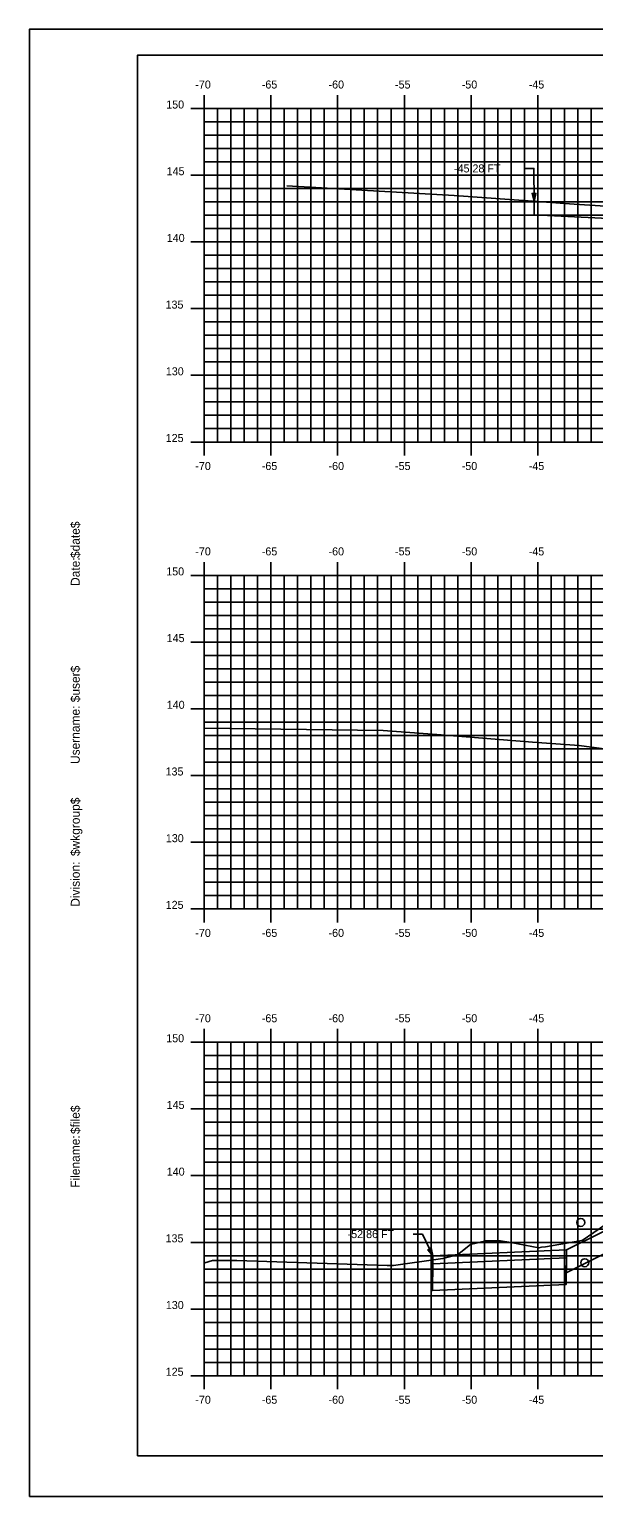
# Model space of a CAD drawing. Extents: x 1144085 to 1144255, y 608981 to 609091.
# Drawn here: x 1144085.3 to 1144127.5, y 608981.3 to 609091.3 of the extents above; entities that cross this region are included whole.
import ezdxf

# ---------------------------------------------------------------- set-up
doc = ezdxf.new("R2010")
doc.units = 0
for name, color, linetype in [('BORDER', 7, 'Continuous'), ('D_Roadway_SubGrade', 7, 'Continuous'), ('D_Text_Standard', 7, 'Continuous'), ('H_V ANNOTATION', 7, 'Continuous'), ('MAJOR', 7, 'Continuous'), ('MINOR', 7, 'Continuous'), ('PATTERNING', 7, 'Continuous'), ('PLOT BOUNDARY', 7, 'Continuous'), ('S_Drainage_Invert', 7, 'Continuous'), ('S_Roadway_Centerline', 7, 'Continuous')]:
    doc.layers.add(name, color=color, linetype=linetype)

msp = doc.modelspace()

# ---------------------------------------------------------------- linework, layer by layer
msp.add_lwpolyline([(1144123.07, 609078.38), (1144153.35, 609078.29), (1144157.35, 609078.45), (1144168.35, 609078.67), (1144179.35, 609078.45), (1144188.75, 609078.08), (1144196.13, 609075.62), (1144199.13, 609074.62), (1144217.63, 609068.45)])
at = {"layer": 'BORDER'}
msp.add_lwpolyline([(1144093.35, 608984.34), (1144253.35, 608984.34), (1144253.35, 609089.34), (1144093.35, 609089.34)], close=True, dxfattribs=at)
at = {"layer": 'D_Roadway_SubGrade'}
msp.add_lwpolyline([(1144123.07, 609077.38), (1144153.35, 609075.87), (1144157.35, 609075.95), (1144157.35, 609078.04), (1144157.35, 609078.2), (1144153.35, 609078.04), (1144153.35, 609078.29), (1144123.07, 609078.38)], close=True, dxfattribs=at)
at = {"layer": 'D_Text_Standard'}
for points in [[(1144123.07, 609078.38), (1144123.05, 609080.85), (1144122.37, 609080.85)], [(1144115.49, 608999.33), (1144114.7, 609000.96), (1144114.02, 609000.96)]]:
    msp.add_lwpolyline(points, dxfattribs=at)
for points in [[(1144123.07, 609078.38), (1144122.92, 609078.97), (1144123.21, 609078.97)], [(1144115.49, 608999.33), (1144115.11, 608999.79), (1144115.37, 608999.92)]]:
    msp.add_lwpolyline(points, close=True, dxfattribs=at)
at = {"layer": 'MAJOR'}
for p, q in [((1144098.35, 609086.34), (1144098.35, 609085.34)), ((1144103.35, 609086.34), (1144103.35, 609085.34)), ((1144108.35, 609086.34), (1144108.35, 609085.34)), ((1144113.35, 609086.34), (1144113.35, 609085.34)), ((1144118.35, 609086.34), (1144118.35, 609085.34)), ((1144123.35, 609086.34), (1144123.35, 609085.34)), ((1144097.35, 609085.34), (1144098.35, 609085.34)), ((1144098.35, 609085.34), (1144238.35, 609085.34)), ((1144098.35, 609060.34), (1144098.35, 609085.34)), ((1144098.35, 609060.34), (1144098.35, 609085.34)), ((1144098.35, 609085.34), (1144238.35, 609085.34)), ((1144103.35, 609060.34), (1144103.35, 609085.34)), ((1144108.35, 609060.34), (1144108.35, 609085.34)), ((1144113.35, 609060.34), (1144113.35, 609085.34)), ((1144118.35, 609060.34), (1144118.35, 609085.34)), ((1144123.35, 609060.34), (1144123.35, 609085.34)), ((1144097.35, 609080.34), (1144098.35, 609080.34)), ((1144098.35, 609080.34), (1144238.35, 609080.34)), ((1144097.35, 609075.34), (1144098.35, 609075.34)), ((1144098.35, 609075.34), (1144238.35, 609075.34)), ((1144097.35, 609070.34), (1144098.35, 609070.34)), ((1144098.35, 609070.34), (1144238.35, 609070.34)), ((1144097.35, 609065.34), (1144098.35, 609065.34)), ((1144098.35, 609065.34), (1144238.35, 609065.34)), ((1144097.35, 609060.34), (1144098.35, 609060.34)), ((1144098.35, 609060.34), (1144238.35, 609060.34)), ((1144098.35, 609060.34), (1144238.35, 609060.34)), ((1144098.35, 609059.33), (1144098.35, 609060.34)), ((1144103.35, 609059.33), (1144103.35, 609060.34)), ((1144108.35, 609059.33), (1144108.35, 609060.34)), ((1144113.35, 609059.33), (1144113.35, 609060.34)), ((1144118.35, 609059.33), (1144118.35, 609060.34)), ((1144123.35, 609059.33), (1144123.35, 609060.34)), ((1144098.35, 609051.34), (1144098.35, 609050.34)), ((1144103.35, 609051.34), (1144103.35, 609050.34)), ((1144108.35, 609051.34), (1144108.35, 609050.34)), ((1144113.35, 609051.34), (1144113.35, 609050.34)), ((1144118.35, 609051.34), (1144118.35, 609050.34)), ((1144123.35, 609051.34), (1144123.35, 609050.34)), ((1144097.35, 609050.34), (1144098.35, 609050.34)), ((1144098.35, 609050.34), (1144238.35, 609050.34)), ((1144098.35, 609025.34), (1144098.35, 609050.34)), ((1144098.35, 609025.34), (1144098.35, 609050.34)), ((1144098.35, 609050.34), (1144238.35, 609050.34)), ((1144103.35, 609025.34), (1144103.35, 609050.34)), ((1144108.35, 609025.34), (1144108.35, 609050.34)), ((1144113.35, 609025.34), (1144113.35, 609050.34)), ((1144118.35, 609025.34), (1144118.35, 609050.34)), ((1144123.35, 609025.34), (1144123.35, 609050.34)), ((1144097.35, 609045.34), (1144098.35, 609045.34)), ((1144098.35, 609045.34), (1144238.35, 609045.34)), ((1144097.35, 609040.34), (1144098.35, 609040.34)), ((1144098.35, 609040.34), (1144238.35, 609040.34)), ((1144097.35, 609035.34), (1144098.35, 609035.34)), ((1144098.35, 609035.34), (1144238.35, 609035.34)), ((1144097.35, 609030.34), (1144098.35, 609030.34)), ((1144098.35, 609030.34), (1144238.35, 609030.34)), ((1144097.35, 609025.34), (1144098.35, 609025.34)), ((1144098.35, 609025.34), (1144238.35, 609025.34)), ((1144098.35, 609025.34), (1144238.35, 609025.34)), ((1144098.35, 609024.33), (1144098.35, 609025.34)), ((1144103.35, 609024.33), (1144103.35, 609025.34)), ((1144108.35, 609024.33), (1144108.35, 609025.34)), ((1144113.35, 609024.33), (1144113.35, 609025.34)), ((1144118.35, 609024.33), (1144118.35, 609025.34)), ((1144123.35, 609024.33), (1144123.35, 609025.34)), ((1144098.35, 609016.34), (1144098.35, 609015.34)), ((1144103.35, 609016.34), (1144103.35, 609015.34)), ((1144108.35, 609016.34), (1144108.35, 609015.34)), ((1144113.35, 609016.34), (1144113.35, 609015.34)), ((1144118.35, 609016.34), (1144118.35, 609015.34)), ((1144123.35, 609016.34), (1144123.35, 609015.34)), ((1144097.35, 609015.34), (1144098.35, 609015.34)), ((1144098.35, 609015.34), (1144238.35, 609015.34)), ((1144098.35, 608990.34), (1144098.35, 609015.34)), ((1144098.35, 608990.34), (1144098.35, 609015.34)), ((1144098.35, 609015.34), (1144238.35, 609015.34)), ((1144103.35, 608990.34), (1144103.35, 609015.34)), ((1144108.35, 608990.34), (1144108.35, 609015.34)), ((1144113.35, 608990.34), (1144113.35, 609015.34)), ((1144118.35, 608990.34), (1144118.35, 609015.34)), ((1144123.35, 608990.34), (1144123.35, 609015.34)), ((1144097.35, 609010.34), (1144098.35, 609010.34)), ((1144098.35, 609010.34), (1144238.35, 609010.34)), ((1144097.35, 609005.34), (1144098.35, 609005.34)), ((1144098.35, 609005.34), (1144238.35, 609005.34)), ((1144097.35, 609000.34), (1144098.35, 609000.34)), ((1144098.35, 609000.34), (1144238.35, 609000.34)), ((1144097.35, 608995.34), (1144098.35, 608995.34)), ((1144098.35, 608995.34), (1144238.35, 608995.34)), ((1144097.35, 608990.34), (1144098.35, 608990.34)), ((1144098.35, 608990.34), (1144238.35, 608990.34)), ((1144098.35, 608990.34), (1144238.35, 608990.34)), ((1144098.35, 608989.33), (1144098.35, 608990.34)), ((1144103.35, 608989.33), (1144103.35, 608990.34)), ((1144108.35, 608989.33), (1144108.35, 608990.34)), ((1144113.35, 608989.33), (1144113.35, 608990.34)), ((1144118.35, 608989.33), (1144118.35, 608990.34)), ((1144123.35, 608989.33), (1144123.35, 608990.34))]:
    msp.add_line(p, q, dxfattribs=at)
at = {"layer": 'MINOR'}
for p, q in [((1144098.35, 609084.34), (1144238.35, 609084.34)), ((1144098.35, 609084.34), (1144099.35, 609084.34)), ((1144099.35, 609060.34), (1144099.35, 609085.34)), ((1144100.35, 609060.34), (1144100.35, 609085.34)), ((1144101.35, 609060.34), (1144101.35, 609085.34)), ((1144102.35, 609060.34), (1144102.35, 609085.34)), ((1144104.35, 609060.34), (1144104.35, 609085.34)), ((1144105.35, 609060.34), (1144105.35, 609085.34)), ((1144106.35, 609060.34), (1144106.35, 609085.34)), ((1144107.35, 609060.34), (1144107.35, 609085.34)), ((1144109.35, 609060.34), (1144109.35, 609085.34)), ((1144110.35, 609060.34), (1144110.35, 609085.34)), ((1144111.35, 609060.34), (1144111.35, 609085.34)), ((1144112.35, 609060.34), (1144112.35, 609085.34)), ((1144114.35, 609060.34), (1144114.35, 609085.34)), ((1144115.35, 609060.34), (1144115.35, 609085.34)), ((1144116.35, 609060.34), (1144116.35, 609085.34)), ((1144117.35, 609060.34), (1144117.35, 609085.34)), ((1144119.35, 609060.34), (1144119.35, 609085.34)), ((1144120.35, 609060.34), (1144120.35, 609085.34)), ((1144121.35, 609060.34), (1144121.35, 609085.34)), ((1144122.35, 609060.34), (1144122.35, 609085.34)), ((1144124.35, 609060.34), (1144124.35, 609085.34)), ((1144125.35, 609060.34), (1144125.35, 609085.34)), ((1144126.35, 609060.34), (1144126.35, 609085.34)), ((1144127.35, 609060.34), (1144127.35, 609085.34)), ((1144098.35, 609083.34), (1144238.35, 609083.34)), ((1144098.35, 609083.34), (1144099.35, 609083.34)), ((1144098.35, 609082.34), (1144238.35, 609082.34)), ((1144098.35, 609082.34), (1144099.35, 609082.34)), ((1144098.35, 609081.34), (1144238.35, 609081.34)), ((1144098.35, 609081.34), (1144099.35, 609081.34)), ((1144098.35, 609079.34), (1144238.35, 609079.34)), ((1144098.35, 609079.34), (1144099.35, 609079.34)), ((1144098.35, 609078.34), (1144238.35, 609078.34)), ((1144098.35, 609078.34), (1144099.35, 609078.34)), ((1144098.35, 609077.34), (1144238.35, 609077.34)), ((1144098.35, 609077.34), (1144099.35, 609077.34)), ((1144098.35, 609076.34), (1144238.35, 609076.34)), ((1144098.35, 609076.34), (1144099.35, 609076.34)), ((1144098.35, 609074.34), (1144238.35, 609074.34)), ((1144098.35, 609074.34), (1144099.35, 609074.34)), ((1144098.35, 609073.34), (1144238.35, 609073.34)), ((1144098.35, 609073.34), (1144099.35, 609073.34)), ((1144098.35, 609072.34), (1144238.35, 609072.34)), ((1144098.35, 609072.34), (1144099.35, 609072.34)), ((1144098.35, 609071.34), (1144238.35, 609071.34)), ((1144098.35, 609071.34), (1144099.35, 609071.34)), ((1144098.35, 609069.34), (1144238.35, 609069.34)), ((1144098.35, 609069.34), (1144099.35, 609069.34)), ((1144098.35, 609068.34), (1144238.35, 609068.34)), ((1144098.35, 609068.34), (1144099.35, 609068.34)), ((1144098.35, 609067.34), (1144238.35, 609067.34)), ((1144098.35, 609067.34), (1144099.35, 609067.34)), ((1144098.35, 609066.34), (1144238.35, 609066.34)), ((1144098.35, 609066.34), (1144099.35, 609066.34)), ((1144098.35, 609064.34), (1144238.35, 609064.34)), ((1144098.35, 609064.34), (1144099.35, 609064.34)), ((1144098.35, 609063.34), (1144238.35, 609063.34)), ((1144098.35, 609063.34), (1144099.35, 609063.34)), ((1144098.35, 609062.34), (1144238.35, 609062.34)), ((1144098.35, 609062.34), (1144099.35, 609062.34)), ((1144098.35, 609061.34), (1144238.35, 609061.34)), ((1144098.35, 609061.34), (1144099.35, 609061.34)), ((1144099.35, 609025.34), (1144099.35, 609050.34)), ((1144100.35, 609025.34), (1144100.35, 609050.34)), ((1144101.35, 609025.34), (1144101.35, 609050.34)), ((1144102.35, 609025.34), (1144102.35, 609050.34)), ((1144104.35, 609025.34), (1144104.35, 609050.34)), ((1144105.35, 609025.34), (1144105.35, 609050.34)), ((1144106.35, 609025.34), (1144106.35, 609050.34)), ((1144107.35, 609025.34), (1144107.35, 609050.34)), ((1144109.35, 609025.34), (1144109.35, 609050.34)), ((1144110.35, 609025.34), (1144110.35, 609050.34)), ((1144111.35, 609025.34), (1144111.35, 609050.34)), ((1144112.35, 609025.34), (1144112.35, 609050.34)), ((1144114.35, 609025.34), (1144114.35, 609050.34)), ((1144115.35, 609025.34), (1144115.35, 609050.34)), ((1144116.35, 609025.34), (1144116.35, 609050.34)), ((1144117.35, 609025.34), (1144117.35, 609050.34)), ((1144119.35, 609025.34), (1144119.35, 609050.34)), ((1144120.35, 609025.34), (1144120.35, 609050.34)), ((1144121.35, 609025.34), (1144121.35, 609050.34)), ((1144122.35, 609025.34), (1144122.35, 609050.34)), ((1144124.35, 609025.34), (1144124.35, 609050.34)), ((1144125.35, 609025.34), (1144125.35, 609050.34)), ((1144126.35, 609025.34), (1144126.35, 609050.34)), ((1144127.35, 609025.34), (1144127.35, 609050.34)), ((1144098.35, 609049.34), (1144238.35, 609049.34)), ((1144098.35, 609049.34), (1144099.35, 609049.34)), ((1144098.35, 609048.34), (1144238.35, 609048.34)), ((1144098.35, 609048.34), (1144099.35, 609048.34)), ((1144098.35, 609047.34), (1144238.35, 609047.34)), ((1144098.35, 609047.34), (1144099.35, 609047.34)), ((1144098.35, 609046.34), (1144238.35, 609046.34)), ((1144098.35, 609046.34), (1144099.35, 609046.34)), ((1144098.35, 609044.34), (1144238.35, 609044.34)), ((1144098.35, 609044.34), (1144099.35, 609044.34)), ((1144098.35, 609043.34), (1144238.35, 609043.34)), ((1144098.35, 609043.34), (1144099.35, 609043.34)), ((1144098.35, 609042.34), (1144238.35, 609042.34)), ((1144098.35, 609042.34), (1144099.35, 609042.34)), ((1144098.35, 609041.34), (1144238.35, 609041.34)), ((1144098.35, 609041.34), (1144099.35, 609041.34)), ((1144098.35, 609039.34), (1144238.35, 609039.34)), ((1144098.35, 609039.34), (1144099.35, 609039.34)), ((1144098.35, 609038.34), (1144238.35, 609038.34)), ((1144098.35, 609038.34), (1144099.35, 609038.34)), ((1144098.35, 609037.34), (1144238.35, 609037.34)), ((1144098.35, 609037.34), (1144099.35, 609037.34)), ((1144098.35, 609036.34), (1144238.35, 609036.34)), ((1144098.35, 609036.34), (1144099.35, 609036.34)), ((1144098.35, 609034.34), (1144238.35, 609034.34)), ((1144098.35, 609034.34), (1144099.35, 609034.34)), ((1144098.35, 609033.34), (1144238.35, 609033.34)), ((1144098.35, 609033.34), (1144099.35, 609033.34)), ((1144098.35, 609032.34), (1144238.35, 609032.34)), ((1144098.35, 609032.34), (1144099.35, 609032.34)), ((1144098.35, 609031.34), (1144238.35, 609031.34)), ((1144098.35, 609031.34), (1144099.35, 609031.34)), ((1144098.35, 609029.34), (1144238.35, 609029.34)), ((1144098.35, 609029.34), (1144099.35, 609029.34)), ((1144098.35, 609028.34), (1144238.35, 609028.34)), ((1144098.35, 609028.34), (1144099.35, 609028.34)), ((1144098.35, 609027.34), (1144238.35, 609027.34)), ((1144098.35, 609027.34), (1144099.35, 609027.34)), ((1144098.35, 609026.34), (1144238.35, 609026.34)), ((1144098.35, 609026.34), (1144099.35, 609026.34)), ((1144099.35, 608990.34), (1144099.35, 609015.34)), ((1144100.35, 608990.34), (1144100.35, 609015.34)), ((1144101.35, 608990.34), (1144101.35, 609015.34)), ((1144102.35, 608990.34), (1144102.35, 609015.34)), ((1144104.35, 608990.34), (1144104.35, 609015.34)), ((1144105.35, 608990.34), (1144105.35, 609015.34)), ((1144106.35, 608990.34), (1144106.35, 609015.34)), ((1144107.35, 608990.34), (1144107.35, 609015.34)), ((1144109.35, 608990.34), (1144109.35, 609015.34)), ((1144110.35, 608990.34), (1144110.35, 609015.34)), ((1144111.35, 608990.34), (1144111.35, 609015.34)), ((1144112.35, 608990.34), (1144112.35, 609015.34)), ((1144114.35, 608990.34), (1144114.35, 609015.34)), ((1144115.35, 608990.34), (1144115.35, 609015.34)), ((1144116.35, 608990.34), (1144116.35, 609015.34)), ((1144117.35, 608990.34), (1144117.35, 609015.34)), ((1144119.35, 608990.34), (1144119.35, 609015.34)), ((1144120.35, 608990.34), (1144120.35, 609015.34)), ((1144121.35, 608990.34), (1144121.35, 609015.34)), ((1144122.35, 608990.34), (1144122.35, 609015.34)), ((1144124.35, 608990.34), (1144124.35, 609015.34)), ((1144125.35, 608990.34), (1144125.35, 609015.34)), ((1144126.35, 608990.34), (1144126.35, 609015.34)), ((1144127.35, 608990.34), (1144127.35, 609015.34)), ((1144098.35, 609014.34), (1144238.35, 609014.34)), ((1144098.35, 609014.34), (1144099.35, 609014.34)), ((1144098.35, 609013.34), (1144238.35, 609013.34)), ((1144098.35, 609013.34), (1144099.35, 609013.34)), ((1144098.35, 609012.34), (1144238.35, 609012.34)), ((1144098.35, 609012.34), (1144099.35, 609012.34)), ((1144098.35, 609011.34), (1144238.35, 609011.34)), ((1144098.35, 609011.34), (1144099.35, 609011.34)), ((1144098.35, 609009.34), (1144238.35, 609009.34)), ((1144098.35, 609009.34), (1144099.35, 609009.34)), ((1144098.35, 609008.34), (1144238.35, 609008.34)), ((1144098.35, 609008.34), (1144099.35, 609008.34)), ((1144098.35, 609007.34), (1144238.35, 609007.34)), ((1144098.35, 609007.34), (1144099.35, 609007.34)), ((1144098.35, 609006.34), (1144238.35, 609006.34)), ((1144098.35, 609006.34), (1144099.35, 609006.34)), ((1144098.35, 609004.34), (1144238.35, 609004.34)), ((1144098.35, 609004.34), (1144099.35, 609004.34)), ((1144098.35, 609003.34), (1144238.35, 609003.34)), ((1144098.35, 609003.34), (1144099.35, 609003.34)), ((1144098.35, 609002.34), (1144238.35, 609002.34)), ((1144098.35, 609002.34), (1144099.35, 609002.34)), ((1144098.35, 609001.34), (1144238.35, 609001.34)), ((1144098.35, 609001.34), (1144099.35, 609001.34)), ((1144098.35, 608999.34), (1144238.35, 608999.34)), ((1144098.35, 608999.34), (1144099.35, 608999.34)), ((1144098.35, 608998.34), (1144238.35, 608998.34)), ((1144098.35, 608998.34), (1144099.35, 608998.34)), ((1144098.35, 608997.34), (1144238.35, 608997.34)), ((1144098.35, 608997.34), (1144099.35, 608997.34)), ((1144098.35, 608996.34), (1144238.35, 608996.34)), ((1144098.35, 608996.34), (1144099.35, 608996.34)), ((1144098.35, 608994.34), (1144238.35, 608994.34)), ((1144098.35, 608994.34), (1144099.35, 608994.34)), ((1144098.35, 608993.34), (1144238.35, 608993.34)), ((1144098.35, 608993.34), (1144099.35, 608993.34)), ((1144098.35, 608992.34), (1144238.35, 608992.34)), ((1144098.35, 608992.34), (1144099.35, 608992.34)), ((1144098.35, 608991.34), (1144238.35, 608991.34)), ((1144098.35, 608991.34), (1144099.35, 608991.34))]:
    msp.add_line(p, q, dxfattribs=at)
at = {"layer": 'PATTERNING'}
for points in [[(1144125.49, 608999.77), (1144133.98, 609003.97), (1144135.77, 609004.86), (1144136.43, 609003.52), (1144125.48, 608998.06), (1144125.49, 608999.17)], [(1144125.49, 608999.77), (1144115.49, 608999.33), (1144115.48, 608998.73), (1144125.49, 608999.17)], [(1144125.49, 608999.17), (1144115.48, 608998.73), (1144115.45, 608996.73), (1144125.46, 608997.17)]]:
    msp.add_lwpolyline(points, close=True, dxfattribs=at)
at = {"layer": 'PLOT BOUNDARY'}
msp.add_lwpolyline([(1144085.26, 608981.28), (1144255.26, 608981.28), (1144255.26, 609091.28), (1144085.26, 609091.28)], close=True, dxfattribs=at)
at = {"layer": 'S_Drainage_Invert'}
for centre in [(1144126.57, 609001.83), (1144126.87, 608998.81)]:
    msp.add_circle(centre, 0.3, dxfattribs=at)
at = {"layer": 'S_Roadway_Centerline'}
for points in [[(1144104.55, 609079.55), (1144117.07, 609078.83), (1144126.07, 609078.18), (1144137.01, 609077.48)], [(1144098.35, 609038.88), (1144111.76, 609038.71), (1144116.1, 609038.38), (1144122.96, 609037.83), (1144126.45, 609037.59), (1144128.5, 609037.32)], [(1144098.35, 608998.82), (1144098.39, 608998.81), (1144098.97, 608998.97), (1144100.81, 608998.99), (1144112.07, 608998.6), (1144112.54, 608998.61), (1144116.24, 608999.12), (1144117.33, 608999.4), (1144118.31, 609000.19), (1144119.45, 609000.46), (1144120.55, 609000.46), (1144121.33, 609000.32), (1144123.43, 608999.92), (1144123.63, 608999.97), (1144123.92, 609000.01), (1144126.64, 609000.49), (1144126.68, 609000.47), (1144128.43, 609001.68)]]:
    msp.add_lwpolyline(points, dxfattribs=at)

# ---------------------------------------------------------------- texts
at = {"layer": 'BORDER'}
for s, p in [('$date$', (1144089.03, 609051.64)), ('Date:', (1144089.03, 609049.55)), ('$user$', (1144089.03, 609040.83)), ('Username:', (1144089.03, 609036.2)), ('$wkgroup$', (1144089.03, 609029.3)), ('Division:', (1144089.03, 609025.5)), ('$file$', (1144089.03, 609008.46)), ('Filename:', (1144089.03, 609004.43))]:
    msp.add_text(s, height=0.67, rotation=90, dxfattribs=at).set_placement(p)
at = {"layer": 'D_Text_Standard'}
for s, p in [('-45.28 FT', (1144117.07, 609080.55)), ('-52.86 FT', (1144109.1, 609000.66))]:
    msp.add_text(s, height=0.6, dxfattribs=at).set_placement(p)
at = {"layer": 'H_V ANNOTATION'}
for s, p in [('-70', (1144097.69, 609086.84)), ('-65', (1144102.67, 609086.84)), ('-60', (1144107.67, 609086.84)), ('-55', (1144112.65, 609086.84)), ('-50', (1144117.65, 609086.84)), ('-45', (1144122.67, 609086.84)), ('150', (1144095.51, 609085.34)), ('145', (1144095.54, 609080.34)), ('140', (1144095.55, 609075.34)), ('135', (1144095.46, 609070.34)), ('130', (1144095.48, 609065.34)), ('125', (1144095.47, 609060.34)), ('-70', (1144097.69, 609058.24)), ('-65', (1144102.67, 609058.24)), ('-60', (1144107.67, 609058.24)), ('-55', (1144112.65, 609058.24)), ('-50', (1144117.65, 609058.24)), ('-45', (1144122.67, 609058.24)), ('-70', (1144097.69, 609051.84)), ('-65', (1144102.67, 609051.84)), ('-60', (1144107.67, 609051.84)), ('-55', (1144112.65, 609051.84)), ('-50', (1144117.65, 609051.84)), ('-45', (1144122.67, 609051.84)), ('150', (1144095.51, 609050.34)), ('145', (1144095.54, 609045.34)), ('140', (1144095.55, 609040.34)), ('135', (1144095.46, 609035.34)), ('130', (1144095.48, 609030.34)), ('125', (1144095.47, 609025.34)), ('-70', (1144097.69, 609023.24)), ('-65', (1144102.67, 609023.24)), ('-60', (1144107.67, 609023.24)), ('-55', (1144112.65, 609023.24)), ('-50', (1144117.65, 609023.24)), ('-45', (1144122.67, 609023.24)), ('-70', (1144097.69, 609016.84)), ('-65', (1144102.67, 609016.84)), ('-60', (1144107.67, 609016.84)), ('-55', (1144112.65, 609016.84)), ('-50', (1144117.65, 609016.84)), ('-45', (1144122.67, 609016.84)), ('150', (1144095.51, 609015.34)), ('145', (1144095.54, 609010.34)), ('140', (1144095.55, 609005.34)), ('135', (1144095.46, 609000.34)), ('130', (1144095.48, 608995.34)), ('125', (1144095.47, 608990.34)), ('-70', (1144097.69, 608988.24)), ('-65', (1144102.67, 608988.24)), ('-60', (1144107.67, 608988.24)), ('-55', (1144112.65, 608988.24)), ('-50', (1144117.65, 608988.24)), ('-45', (1144122.67, 608988.24))]:
    msp.add_text(s, height=0.6, dxfattribs=at).set_placement(p)
at = {"layer": 'MAJOR'}
for p in [(1144098.34, 609060.34), (1144098.34, 609025.34), (1144098.34, 608990.34)]:
    msp.add_text('-', height=0.006, dxfattribs=at).set_placement(p)

doc.saveas('drawing.dxf')
